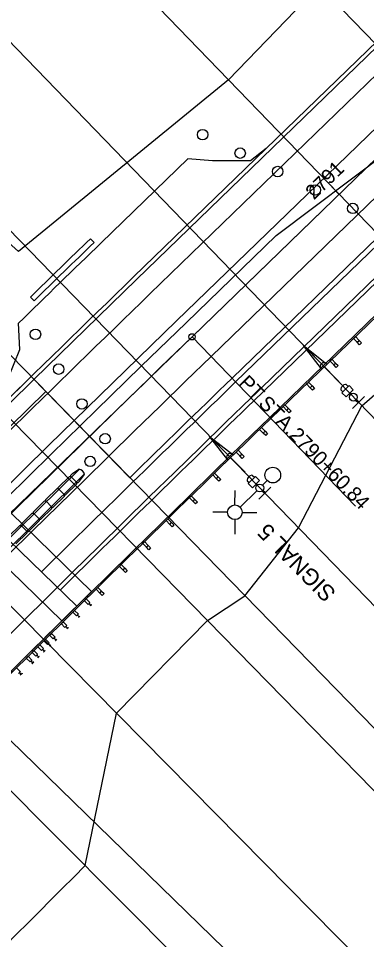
# Model space of a CAD drawing. Extents: x 2376379 to 2383101, y 559608 to 561720.
# Drawn here: x 2377157.2 to 2377223.9, y 561284 to 561460 of the extents above; entities that cross this region are included whole.
import ezdxf

# ---------------------------------------------------------------- set-up
doc = ezdxf.new("R2010")
doc.units = 0
for name, color, linetype in [('BR_X_SV_Bottom_of_Beam', 7, 'Continuous'), ('BR_X_SV_Deck_Top', 7, 'Continuous'), ('BR_X_SV_Pier', 7, 'Continuous'), ('DR_X_Headwall', 7, 'Continuous'), ('DR_X_Storm_Sewer', 7, 'Continuous'), ('DT_X_Contour_Minor', 7, 'Continuous'), ('DT_X_Contour_Text', 7, 'Continuous'), ('DT_X_Terrain_Ground_Line', 7, 'Continuous'), ('DT_X_Void', 7, 'Continuous'), ('HY_X_Spring_Cells', 7, 'Continuous'), ('HY_X_Water_Edge', 7, 'Continuous'), ('PM_X_CL_Dashed', 7, 'Continuous'), ('PM_X_Surveyed_Line', 7, 'Continuous'), ('PV_X_COP', 7, 'Continuous'), ('PV_X_EOP', 7, 'Continuous'), ('RD_X_Cells', 7, 'Continuous'), ('SV_X_Text', 7, 'Continuous')]:
    doc.layers.add(name, color=color, linetype=linetype)

msp = doc.modelspace()

# ---------------------------------------------------------------- linework, layer by layer
at = {"layer": 'BR_X_SV_Bottom_of_Beam'}
for p, q in [((2377194.11, 561395.38), (2377246.68, 561446.25)), ((2377254.33, 561438.35), (2377201.76, 561387.47)), ((2377150.72, 561355.99), (2377168.89, 561373.86)), ((2377167.55, 561373.01), (2377168.8, 561373.88)), ((2377169.83, 561372.91), (2377151.65, 561355.04)), ((2377164.86, 561370.37), (2377167, 561372.47)), ((2377167, 561372.47), (2377167.24, 561372.47)), ((2377167.24, 561372.7), (2377167.55, 561373.01)), ((2377167.24, 561372.47), (2377167.24, 561372.7)), ((2377167.24, 561372.47), (2377168.41, 561371.28)), ((2377168.95, 561371.58), (2377168.64, 561371.28)), ((2377168.95, 561371.58), (2377169.85, 561372.81)), ((2377162.49, 561368.03), (2377164.62, 561370.13)), ((2377164.62, 561370.13), (2377164.86, 561370.13)), ((2377164.86, 561370.13), (2377164.86, 561370.37)), ((2377164.86, 561370.13), (2377166.03, 561368.94)), ((2377168.4, 561371.04), (2377166.26, 561368.94)), ((2377168.4, 561371.04), (2377168.41, 561371.28)), ((2377168.41, 561371.28), (2377168.64, 561371.28)), ((2377162.48, 561367.79), (2377162.49, 561368.03)), ((2377166.03, 561368.71), (2377163.89, 561366.6)), ((2377166.03, 561368.71), (2377166.03, 561368.94)), ((2377166.03, 561368.94), (2377166.26, 561368.94)), ((2377162.25, 561367.8), (2377160.11, 561365.69)), ((2377163.65, 561366.37), (2377161.51, 561364.27)), ((2377162.25, 561367.8), (2377162.48, 561367.79)), ((2377162.48, 561367.79), (2377163.65, 561366.61)), ((2377163.65, 561366.37), (2377163.65, 561366.61)), ((2377163.65, 561366.61), (2377163.89, 561366.6)), ((2377159.87, 561365.46), (2377157.73, 561363.36)), ((2377159.87, 561365.46), (2377160.11, 561365.46)), ((2377160.11, 561365.46), (2377160.11, 561365.69)), ((2377160.11, 561365.46), (2377161.28, 561364.27)), ((2377157.49, 561363.12), (2377155.35, 561361.02)), ((2377157.49, 561363.12), (2377157.73, 561363.12)), ((2377157.73, 561363.12), (2377157.73, 561363.36)), ((2377157.73, 561363.12), (2377158.9, 561361.93)), ((2377161.27, 561364.03), (2377159.13, 561361.93)), ((2377161.27, 561364.03), (2377161.28, 561364.27)), ((2377161.28, 561364.27), (2377161.51, 561364.27)), ((2377158.9, 561361.7), (2377156.76, 561359.59)), ((2377158.9, 561361.7), (2377158.9, 561361.93)), ((2377158.9, 561361.93), (2377159.13, 561361.93))]:
    msp.add_line(p, q, dxfattribs=at)
for centre in [(2377192.48, 561437.79), (2377199.66, 561434.26), (2377206.84, 561430.74), (2377214.03, 561427.21), (2377221.21, 561423.69), (2377160.49, 561399.63), (2377164.93, 561392.98), (2377169.38, 561386.33), (2377173.82, 561379.67), (2377170.96, 561375.34)]:
    msp.add_circle(centre, 1, dxfattribs=at)
for centre, radius, start, end in [((2381174.86, 557281.31), 5724.68, 134.05646, 138.41459), ((2381174.86, 557281.31), 5713.68, 134.05646, 138.41459), ((2377168.53, 561372.57), 1.34, 10.3385, 78.6899)]:
    msp.add_arc(centre, radius, start, end, dxfattribs=at)
at = {"layer": 'BR_X_SV_Deck_Top'}
for p, q in [((2377264.5, 561486.8), (2377182.46, 561407.42)), ((2377179.33, 561410.65), (2377236.22, 561465.7))]:
    msp.add_line(p, q, dxfattribs=at)
for radius, end in [(5745.93, 134.827633), (5741.43, 134.826849)]:
    msp.add_arc((2381174.86, 557281.31), radius, 134.056462, end, dxfattribs=at)
at = {"layer": 'BR_X_SV_Pier'}
for p, q in [((2377218.54, 561390.64), (2377211.75, 561397.51)), ((2377215.2, 561393.01), (2377211.75, 561397.51)), ((2377211.75, 561397.51), (2377216.2, 561394)), ((2377218.94, 561388.99), (2377219.28, 561388.65)), ((2377218.94, 561388.99), (2377219.28, 561388.65)), ((2377220.49, 561389.83), (2377219.11, 561388.47)), ((2377221.3, 561389.02), (2377219.92, 561387.65)), ((2377219.97, 561390.01), (2377220.31, 561389.66)), ((2377219.97, 561390.01), (2377220.31, 561389.66)), ((2377220.49, 561389.83), (2377221.3, 561389.02)), ((2377219.11, 561388.47), (2377219.92, 561387.65)), ((2377220.71, 561388.06), (2377220.52, 561388.25)), ((2377220.71, 561388.06), (2377220.52, 561388.25)), ((2377220.88, 561388.23), (2377220.69, 561388.42)), ((2377220.88, 561388.23), (2377220.69, 561388.42)), ((2377223.46, 561387.76), (2377221.16, 561385.48)), ((2377222.23, 561386.53), (2377221.76, 561387)), ((2377222.23, 561386.53), (2377221.76, 561387)), ((2377222.4, 561386.7), (2377221.93, 561387.17)), ((2377222.4, 561386.7), (2377221.93, 561387.17)), ((2377200.62, 561373.27), (2377193.82, 561380.13)), ((2377197.28, 561375.64), (2377193.82, 561380.13)), ((2377193.82, 561380.13), (2377198.28, 561376.63)), ((2377201.03, 561371.63), (2377201.37, 561371.29)), ((2377201.03, 561371.63), (2377201.37, 561371.29)), ((2377202.57, 561372.47), (2377201.2, 561371.11)), ((2377203.38, 561371.66), (2377202, 561370.29)), ((2377202.05, 561372.65), (2377202.39, 561372.3)), ((2377202.05, 561372.65), (2377202.39, 561372.3)), ((2377202.57, 561372.47), (2377203.38, 561371.66)), ((2377204.84, 561371.67), (2377203.94, 561370.79)), ((2377198.67, 561367.01), (2377198.7, 561369.81)), ((2377202.86, 561369.73), (2377199.65, 561366.59)), ((2377201.2, 561371.11), (2377202, 561370.29)), ((2377202.79, 561370.7), (2377202.61, 561370.89)), ((2377202.79, 561370.7), (2377202.61, 561370.89)), ((2377202.96, 561370.87), (2377202.78, 561371.06)), ((2377202.96, 561370.87), (2377202.78, 561371.06)), ((2377205.55, 561370.4), (2377203.25, 561368.12)), ((2377204.32, 561369.18), (2377203.85, 561369.65)), ((2377204.32, 561369.18), (2377203.85, 561369.65)), ((2377204.49, 561369.35), (2377204.02, 561369.81)), ((2377204.49, 561369.35), (2377204.02, 561369.81)), ((2377197.25, 561365.62), (2377194.45, 561365.65)), ((2377200.05, 561365.59), (2377202.85, 561365.56)), ((2377198.64, 561364.21), (2377198.61, 561361.41))]:
    msp.add_line(p, q, dxfattribs=at)
for centre, radius in [((2377221.32, 561387.62), 0.757), ((2377205.91, 561372.72), 1.5), ((2377203.41, 561370.26), 0.757), ((2377198.65, 561365.61), 1.4)]:
    msp.add_circle(centre, radius, dxfattribs=at)
for centre, start, end in [((2377215.7, 561393.5), 44.64, 224.64), ((2377197.78, 561376.14), 44.7484, 224.7484)]:
    msp.add_arc(centre, 0.702, start, end, dxfattribs=at)
for centre, major_axis in [((2377219.46, 561389.5), (0.512, 0.507)), ((2377219.46, 561389.5), (0.512, 0.507)), ((2377201.54, 561372.14), (0.511, 0.508)), ((2377201.54, 561372.14), (0.511, 0.508))]:
    msp.add_ellipse(centre, major_axis=major_axis, ratio=0.45371, start_param=0, end_param=3.141593, dxfattribs=at)
at = {"layer": 'DR_X_Headwall'}
for p, q in [((2377259.17, 561441.98), (2377202.28, 561386.93)), ((2377162.47, 561388.68), (2377159.67, 561391.54))]:
    msp.add_line(p, q, dxfattribs=at)
for radius, start, end in [(5745.93, 134.329872, 134.579856), (5712.93, 134.05646, 134.57614)]:
    msp.add_arc((2381174.86, 557281.31), radius, start, end, dxfattribs=at)
at = {"layer": 'DR_X_Storm_Sewer'}
msp.add_line((2377138.25, 561376.92), (2377168.38, 561347.65), dxfattribs=at)
msp.add_arc((2381174.92, 557281.26), 5708.58, 134.5752, 134.82612, dxfattribs=at)
at = {"layer": 'DT_X_Contour_Minor'}
for p, q in [((2377176.03, 561327.2), (2377193.42, 561344.92)), ((2377170.01, 561298.09), (2377176.03, 561327.2))]:
    msp.add_line(p, q, dxfattribs=at)
for points in [[(2377249.6, 561502.2), (2377232.2, 561484.23), (2377197.43, 561448.26), (2377157.26, 561415.43), (2377142.94, 561428.27), (2377125.48, 561435.43), (2377091.18, 561438.87), (2377089.8, 561425.09), (2377128.5, 561421.22), (2377141.3, 561398.11), (2377119.87, 561384.02)], [(2377210.81, 561362.63), (2377222.93, 561385.95), (2377241.81, 561402.39), (2377260.6, 561418.93), (2377281.24, 561433.55), (2377291.66, 561458.74)], [(2377193.42, 561344.92), (2377200.56, 561349.68), (2377210.81, 561362.63)]]:
    msp.add_lwpolyline(points, dxfattribs=at)
msp.add_arc((2381174.86, 557281.31), 5672.16, 134.91481, 136.91469, dxfattribs=at)
at = {"layer": 'DT_X_Contour_Text'}
msp.add_line((2377189.67, 561433.18), (2377173.07, 561417.12), dxfattribs=at)
for points in [[(2377204.63, 561435.13), (2377201.67, 561432.81), (2377194.34, 561432.79), (2377189.67, 561433.18)], [(2377151.27, 561383.32), (2377154.24, 561388.69), (2377157.47, 561396.72), (2377157.25, 561401.75)]]:
    msp.add_lwpolyline(points, dxfattribs=at)
msp.add_arc((2381174.86, 557281.31), 5754.93, 134.056462, 134.276067, dxfattribs=at)
at = {"layer": 'DT_X_Terrain_Ground_Line'}
for p, q in [((2377141.1, 561379.73), (2377171.23, 561350.45)), ((2377135.4, 561374.11), (2377165.53, 561344.84))]:
    msp.add_line(p, q, dxfattribs=at)
msp.add_arc((2381174.86, 557281.31), 5708.5, 134.53502, 134.61533, dxfattribs=at)
at = {"layer": 'DT_X_Void'}
for p, q in [((2377171, 561417.9), (2377171.7, 561417.18)), ((2377159.52, 561406.75), (2377160.22, 561406.04))]:
    msp.add_line(p, q, dxfattribs=at)
for radius in [5756.93, 5755.93]:
    msp.add_arc((2381174.86, 557281.31), radius, 134.065868, 134.225135, dxfattribs=at)
at = {"layer": 'HY_X_Spring_Cells'}
msp.add_line((2377190.46, 561399.15), (2377221.75, 561366.81), dxfattribs=at)
msp.add_circle((2377190.46, 561399.15), 0.6, dxfattribs=at)
at = {"layer": 'HY_X_Water_Edge'}
msp.add_line((2377054.07, 561420.72), (2377215.82, 561263.58), dxfattribs=at)
at = {"layer": 'PM_X_CL_Dashed'}
for p, q in [((2377241.55, 561418.78), (2377205.36, 561383.75)), ((2377205.55, 561383.55), (2377241.75, 561418.58)), ((2377221.36, 561398.84), (2377221.72, 561399.19)), ((2377222.05, 561398.13), (2377221.36, 561398.84)), ((2377222.41, 561398.47), (2377221.72, 561399.19)), ((2377216.87, 561394.5), (2377217.23, 561394.85)), ((2377217.56, 561393.78), (2377216.87, 561394.5)), ((2377217.92, 561394.13), (2377217.23, 561394.85)), ((2377212.38, 561390.15), (2377212.73, 561390.5)), ((2377213.07, 561389.43), (2377212.38, 561390.15)), ((2377213.43, 561389.78), (2377212.73, 561390.5)), ((2377207.88, 561385.81), (2377208.24, 561386.15)), ((2377208.58, 561385.09), (2377207.88, 561385.81)), ((2377208.94, 561385.44), (2377208.24, 561386.15)), ((2377203.39, 561381.46), (2377203.75, 561381.81)), ((2377204.09, 561380.74), (2377203.39, 561381.46)), ((2377204.45, 561381.09), (2377203.75, 561381.81)), ((2377198.91, 561377.11), (2377199.27, 561377.46)), ((2377199.6, 561376.39), (2377198.91, 561377.11)), ((2377199.96, 561376.74), (2377199.27, 561377.46)), ((2377194.43, 561372.75), (2377194.78, 561373.1)), ((2377195.12, 561372.04), (2377194.43, 561372.75)), ((2377195.48, 561372.39), (2377194.78, 561373.1)), ((2377189.95, 561368.39), (2377190.31, 561368.74)), ((2377190.65, 561367.68), (2377189.95, 561368.39)), ((2377191, 561368.03), (2377190.31, 561368.74)), ((2377185.48, 561364.03), (2377185.83, 561364.38)), ((2377186.53, 561363.66), (2377185.83, 561364.38)), ((2377186.18, 561363.31), (2377185.48, 561364.03)), ((2377181.01, 561359.66), (2377181.37, 561360.01)), ((2377181.71, 561358.95), (2377181.01, 561359.66)), ((2377182.07, 561359.29), (2377181.37, 561360.01)), ((2377176.55, 561355.28), (2377176.9, 561355.64)), ((2377177.61, 561354.92), (2377176.9, 561355.64)), ((2377177.25, 561354.57), (2377176.55, 561355.28)), ((2377172.09, 561350.91), (2377172.45, 561351.26)), ((2377172.79, 561350.19), (2377172.09, 561350.91)), ((2377173.15, 561350.54), (2377172.45, 561351.26)), ((2377169.86, 561348.71), (2377170.22, 561349.07)), ((2377170.57, 561348), (2377169.86, 561348.71)), ((2377170.92, 561348.35), (2377170.22, 561349.07)), ((2377167.64, 561346.52), (2377167.99, 561346.87)), ((2377168.7, 561346.16), (2377167.99, 561346.87)), ((2377170.57, 561348), (2377170.63, 561348.06)), ((2377170.86, 561348.29), (2377170.63, 561348.06)), ((2377170.63, 561348.06), (2377170.64, 561348.05)), ((2377170.75, 561348.16), (2377170.64, 561348.05)), ((2377171.07, 561347.83), (2377170.75, 561348.16)), ((2377170.87, 561348.28), (2377170.76, 561348.17)), ((2377171.08, 561347.84), (2377170.76, 561348.17)), ((2377170.86, 561348.29), (2377170.92, 561348.35)), ((2377170.87, 561348.28), (2377170.86, 561348.29)), ((2377171.07, 561347.83), (2377170.96, 561347.72)), ((2377170.96, 561347.72), (2377170.97, 561347.71)), ((2377171.21, 561347.94), (2377170.97, 561347.71)), ((2377171.19, 561347.95), (2377171.08, 561347.84)), ((2377171.19, 561347.95), (2377171.21, 561347.94)), ((2377168.34, 561345.81), (2377167.64, 561346.52)), ((2377168.34, 561345.81), (2377168.4, 561345.87)), ((2377168.63, 561346.1), (2377168.4, 561345.87)), ((2377168.4, 561345.87), (2377168.41, 561345.86)), ((2377168.53, 561345.97), (2377168.41, 561345.86)), ((2377168.85, 561345.64), (2377168.53, 561345.97)), ((2377168.65, 561346.09), (2377168.54, 561345.98)), ((2377168.86, 561345.65), (2377168.54, 561345.98)), ((2377168.63, 561346.1), (2377168.7, 561346.16)), ((2377168.65, 561346.09), (2377168.63, 561346.1)), ((2377168.85, 561345.64), (2377168.73, 561345.53)), ((2377168.73, 561345.53), (2377168.75, 561345.52)), ((2377168.98, 561345.75), (2377168.75, 561345.52)), ((2377168.97, 561345.76), (2377168.86, 561345.65)), ((2377168.97, 561345.76), (2377168.98, 561345.75)), ((2377165.41, 561344.33), (2377165.77, 561344.68)), ((2377166.12, 561343.62), (2377165.41, 561344.33)), ((2377166.47, 561343.97), (2377165.77, 561344.68)), ((2377166.12, 561343.62), (2377166.18, 561343.68)), ((2377166.41, 561343.91), (2377166.18, 561343.68)), ((2377166.18, 561343.68), (2377166.19, 561343.66)), ((2377166.3, 561343.77), (2377166.19, 561343.66)), ((2377166.62, 561343.45), (2377166.3, 561343.77)), ((2377166.42, 561343.89), (2377166.31, 561343.78)), ((2377166.63, 561343.46), (2377166.31, 561343.78)), ((2377166.41, 561343.91), (2377166.47, 561343.97)), ((2377166.42, 561343.89), (2377166.41, 561343.91)), ((2377166.62, 561343.45), (2377166.51, 561343.34)), ((2377166.51, 561343.34), (2377166.52, 561343.33)), ((2377166.76, 561343.56), (2377166.52, 561343.33)), ((2377166.74, 561343.57), (2377166.63, 561343.46)), ((2377166.74, 561343.57), (2377166.76, 561343.56)), ((2377163.19, 561342.13), (2377163.55, 561342.48)), ((2377163.89, 561341.42), (2377163.19, 561342.13)), ((2377164.25, 561341.77), (2377163.55, 561342.48)), ((2377163.89, 561341.42), (2377163.95, 561341.48)), ((2377164.19, 561341.71), (2377163.95, 561341.48)), ((2377163.95, 561341.48), (2377163.97, 561341.47)), ((2377164.08, 561341.58), (2377163.97, 561341.47)), ((2377164.4, 561341.25), (2377164.08, 561341.58)), ((2377164.2, 561341.7), (2377164.09, 561341.59)), ((2377164.41, 561341.26), (2377164.09, 561341.59)), ((2377164.19, 561341.71), (2377164.25, 561341.77)), ((2377164.2, 561341.7), (2377164.19, 561341.71)), ((2377160.97, 561339.93), (2377161.32, 561340.29)), ((2377161.67, 561339.22), (2377160.97, 561339.93)), ((2377162.02, 561339.57), (2377161.32, 561340.29)), ((2377162.08, 561341.03), (2377162.43, 561341.38)), ((2377162.78, 561340.32), (2377162.08, 561341.03)), ((2377163.14, 561340.67), (2377162.43, 561341.38)), ((2377162.78, 561340.32), (2377162.84, 561340.38)), ((2377163.08, 561340.61), (2377162.84, 561340.38)), ((2377162.84, 561340.38), (2377162.85, 561340.37)), ((2377162.97, 561340.48), (2377162.85, 561340.37)), ((2377163.29, 561340.16), (2377162.97, 561340.48)), ((2377163.09, 561340.6), (2377162.98, 561340.49)), ((2377163.3, 561340.17), (2377162.98, 561340.49)), ((2377163.08, 561340.61), (2377163.14, 561340.67)), ((2377163.09, 561340.6), (2377163.08, 561340.61)), ((2377163.29, 561340.16), (2377163.17, 561340.05)), ((2377163.17, 561340.05), (2377163.19, 561340.03)), ((2377163.42, 561340.26), (2377163.19, 561340.03)), ((2377163.41, 561340.28), (2377163.3, 561340.17)), ((2377163.41, 561340.28), (2377163.42, 561340.26)), ((2377164.4, 561341.25), (2377164.29, 561341.14)), ((2377164.29, 561341.14), (2377164.3, 561341.13)), ((2377164.53, 561341.36), (2377164.3, 561341.13)), ((2377164.52, 561341.37), (2377164.41, 561341.26)), ((2377164.52, 561341.37), (2377164.53, 561341.36)), ((2377158.74, 561337.73), (2377159.1, 561338.09)), ((2377159.8, 561337.38), (2377159.1, 561338.09)), ((2377159.85, 561338.83), (2377160.21, 561339.19)), ((2377160.56, 561338.12), (2377159.85, 561338.83)), ((2377160.91, 561338.48), (2377160.21, 561339.19)), ((2377160.56, 561338.12), (2377160.62, 561338.18)), ((2377160.85, 561338.41), (2377160.62, 561338.18)), ((2377160.62, 561338.18), (2377160.63, 561338.17)), ((2377160.74, 561338.28), (2377160.63, 561338.17)), ((2377161.06, 561337.96), (2377160.74, 561338.28)), ((2377160.86, 561338.4), (2377160.75, 561338.29)), ((2377161.07, 561337.97), (2377160.75, 561338.29)), ((2377160.85, 561338.41), (2377160.91, 561338.48)), ((2377160.86, 561338.4), (2377160.85, 561338.41)), ((2377161.06, 561337.96), (2377160.95, 561337.85)), ((2377161.2, 561338.07), (2377160.96, 561337.83)), ((2377161.19, 561338.08), (2377161.07, 561337.97)), ((2377161.19, 561338.08), (2377161.2, 561338.07)), ((2377161.67, 561339.22), (2377161.73, 561339.28)), ((2377161.96, 561339.51), (2377161.73, 561339.28)), ((2377161.73, 561339.28), (2377161.74, 561339.27)), ((2377161.85, 561339.38), (2377161.74, 561339.27)), ((2377162.18, 561339.06), (2377161.85, 561339.38)), ((2377161.98, 561339.5), (2377161.86, 561339.39)), ((2377162.19, 561339.07), (2377161.86, 561339.39)), ((2377161.96, 561339.51), (2377162.02, 561339.57)), ((2377161.98, 561339.5), (2377161.96, 561339.51)), ((2377162.18, 561339.06), (2377162.06, 561338.95)), ((2377162.06, 561338.95), (2377162.08, 561338.93)), ((2377162.31, 561339.16), (2377162.08, 561338.93)), ((2377162.3, 561339.18), (2377162.19, 561339.07)), ((2377162.3, 561339.18), (2377162.31, 561339.16)), ((2377159.45, 561337.02), (2377158.74, 561337.73)), ((2377159.8, 561337.38), (2377159.45, 561337.02)), ((2377159.45, 561337.02), (2377159.46, 561337.01)), ((2377159.63, 561337.18), (2377159.46, 561337.01)), ((2377159.63, 561337.18), (2377159.95, 561336.85)), ((2377159.82, 561337.36), (2377159.65, 561337.19)), ((2377159.65, 561337.19), (2377159.97, 561336.87)), ((2377159.95, 561336.85), (2377159.78, 561336.68)), ((2377159.78, 561336.68), (2377159.8, 561336.67)), ((2377159.8, 561337.38), (2377159.82, 561337.36)), ((2377160.15, 561337.02), (2377159.8, 561336.67)), ((2377160.14, 561337.04), (2377159.97, 561336.87)), ((2377160.14, 561337.04), (2377160.15, 561337.02)), ((2377160.95, 561337.85), (2377160.96, 561337.83)), ((2377157.58, 561335.18), (2377156.88, 561335.89)), ((2377157.58, 561335.18), (2377157.23, 561334.83)), ((2377157.23, 561334.83), (2377157.24, 561334.81)), ((2377157.41, 561334.98), (2377157.24, 561334.81)), ((2377157.41, 561334.98), (2377157.73, 561334.66)), ((2377157.6, 561335.16), (2377157.43, 561334.99)), ((2377157.43, 561334.99), (2377157.75, 561334.67)), ((2377157.73, 561334.66), (2377157.56, 561334.49)), ((2377157.56, 561334.49), (2377157.58, 561334.47)), ((2377157.58, 561335.18), (2377157.6, 561335.16)), ((2377157.93, 561334.82), (2377157.58, 561334.47)), ((2377157.92, 561334.84), (2377157.75, 561334.67)), ((2377157.92, 561334.84), (2377157.93, 561334.82))]:
    msp.add_line(p, q, dxfattribs=at)
for points in [[(2377222.88, 561397.99), (2377222.52, 561397.65), (2377222.05, 561398.13), (2377222.41, 561398.47)], [(2377218.39, 561393.65), (2377218.03, 561393.3), (2377217.56, 561393.78), (2377217.92, 561394.13)], [(2377213.89, 561389.3), (2377213.53, 561388.95), (2377213.07, 561389.43), (2377213.43, 561389.78)], [(2377209.4, 561384.96), (2377209.04, 561384.61), (2377208.58, 561385.09), (2377208.94, 561385.44)], [(2377204.91, 561380.61), (2377204.55, 561380.26), (2377204.09, 561380.74), (2377204.45, 561381.09)], [(2377200.43, 561376.26), (2377200.07, 561375.91), (2377199.6, 561376.39), (2377199.96, 561376.74)], [(2377195.95, 561371.91), (2377195.59, 561371.56), (2377195.12, 561372.04), (2377195.48, 561372.39)], [(2377191.47, 561367.55), (2377191.11, 561367.2), (2377190.65, 561367.68), (2377191, 561368.03)], [(2377187, 561363.19), (2377186.64, 561362.84), (2377186.18, 561363.31), (2377186.53, 561363.66)], [(2377182.53, 561358.82), (2377182.18, 561358.47), (2377181.71, 561358.95), (2377182.07, 561359.29)], [(2377178.07, 561354.45), (2377177.72, 561354.1), (2377177.25, 561354.57), (2377177.61, 561354.92)], [(2377173.62, 561350.07), (2377173.26, 561349.72), (2377172.79, 561350.19), (2377173.15, 561350.54)]]:
    msp.add_lwpolyline(points, close=True, dxfattribs=at)
for centre, radius, start, end in [((2381174.86, 557281.31), 5708.5, 134.05646, 138.73479), ((2381174.92, 557281.26), 5708.3, 134.0565, 134.78388)]:
    msp.add_arc(centre, radius, start, end, dxfattribs=at)
at = {"layer": 'PM_X_Surveyed_Line'}
for p, q in [((2377320.01, 561357.53), (2377153.12, 561530)), ((2377135.16, 561512.62), (2377302.04, 561340.14)), ((2377284.08, 561322.76), (2377117.19, 561495.24)), ((2377099.07, 561477.69), (2377266.28, 561305.53)), ((2377087, 561465.93), (2377254.71, 561294.25)), ((2377080.8, 561459.86), (2377248.76, 561288.43)), ((2377231.31, 561271.27), (2377062.6, 561441.96)), ((2377044.49, 561423.98), (2377213.94, 561254.02))]:
    msp.add_line(p, q, dxfattribs=at)
at = {"layer": 'PV_X_COP'}
for p, q in [((2377206.54, 561418.54), (2377264.14, 561461.75)), ((2377179.85, 561410.11), (2377232.43, 561460.98)), ((2377187.5, 561402.21), (2377240.08, 561453.08)), ((2377197.92, 561410.2), (2377206.54, 561418.54)), ((2377189.3, 561401.85), (2377197.92, 561410.2)), ((2377180.68, 561393.5), (2377189.3, 561401.85)), ((2377172.08, 561385.13), (2377180.68, 561393.5)), ((2377163.5, 561376.74), (2377172.08, 561385.13)), ((2377154.93, 561368.34), (2377163.5, 561376.74))]:
    msp.add_line(p, q, dxfattribs=at)
for radius in [5745.18, 5734.18]:
    msp.add_arc((2381174.86, 557281.31), radius, 134.056462, 138.414594, dxfattribs=at)
at = {"layer": 'PV_X_EOP'}
for p, q in [((2377218.6, 561426.38), (2377217.21, 561427.82)), ((2377182.67, 561391.61), (2377181.84, 561392.47))]:
    msp.add_line(p, q, dxfattribs=at)
at = {"layer": 'RD_X_Cells'}
for p, q in [((2376995.66, 561210.67), (2377447.66, 561648.02)), ((2377190.46, 561399.15), (2377411.73, 561613.26))]:
    msp.add_line(p, q, dxfattribs=at)
msp.add_arc((2381174.86, 557281.31), 5729.93, 134.056462, 139.473129, dxfattribs=at)
msp.add_arc((2381174.86, 557281.31), 5729.93, 134.056462, 139.473129, dxfattribs=at)
at = {"layer": 'SV_X_Text'}
for p, q in [((2377280.15, 561470.63), (2377198.11, 561391.25)), ((2377280.84, 561469.91), (2377198.8, 561390.53)), ((2377178.54, 561372.22), (2377162.47, 561388.68))]:
    msp.add_line(p, q, dxfattribs=at)
for radius, start, end in [(5718.93, 134.05646, 134.32987), (5717.93, 134.05646, 134.57724), (5741.93, 134.329872, 134.582464)]:
    msp.add_arc((2381174.86, 557281.31), radius, start, end, dxfattribs=at)

# ---------------------------------------------------------------- texts
at = {"layer": 'BR_X_SV_Pier'}
msp.add_text('SIGNAL 5', height=3.125, rotation=134.7484, dxfattribs=at).set_placement((2377218.18, 561350.38))
at = {"layer": 'HY_X_Spring_Cells'}
for s, p in [('PT', (2377199.22, 561390.16)), (' STA. ', (2377202.28, 561386.99)), ('2790+60.84', (2377208.86, 561380.2))]:
    msp.add_text(s, height=2.8, rotation=314.0565, dxfattribs=at).set_placement(p)
at = {"layer": 'PV_X_EOP'}
msp.add_text('2791', height=2.8, rotation=44.0565, dxfattribs=at).set_placement((2377213.79, 561425.21))

doc.saveas('drawing.dxf')
